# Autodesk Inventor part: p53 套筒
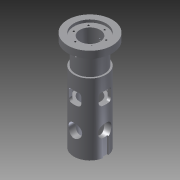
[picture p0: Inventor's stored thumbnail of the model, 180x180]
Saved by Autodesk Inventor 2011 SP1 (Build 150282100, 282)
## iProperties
Created: 2014-01
Part Number: p53 套筒
Document SubType Name: Modeling
Designer: Administrator
Density: 1 g/cm^3
Author: Administrator
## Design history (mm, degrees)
sketch "草图1"
  geometry: C1 r 47.5 at (0, 0); 1 further point
  constraints: 1 centre point, 1 coincident
  dimensions: "d0" = 95 diameter of C1
extrude "拉伸1" new body sketch "草图1" distance "d1" = 270; taper "d2" = 0 deg
hole "Hole1" diameter "d5" = 60; stored, may be unused: countersink angle "d9" = 90 deg, drill point angle "d11" = 118 deg; dims "d3" = 10, "d4" = 10, "d6" = 6, "d7" = 4, "d8" = 2, "d10" = 8
node "工作平面1"
sketch "草图2"
  geometry: L1 (-47.5, 0)-(47.5, 0) reference; L2 (-47.5, 270)-(47.5, 270) reference; L3 (47.5, 0)-(47.5, 270) reference; L4 (-47.5, 0)-(-47.5, 270) reference; L5 (8, 0)-(8, 48.67); L6 (-8, 0)-(-8, 48.67); L7 (-18, 134)-(18, 134); L8 (18, 134)-(18, 170); L9 (18, 170)-(-18, 170); L10 (-18, 170)-(-18, 134); A1 r 20 centre (0, 67) between (8, 48.67) and (-8, 48.67); 3 further points
  constraints: 12 end point, 4 parallel, 2 midpoint, 2 point on circle, 2 point on line, 1 centre point, 1 horizontal, 1 perpendicular, 1 vertical alignment
  dimensions: "d13" = 40 diameter of A1; "d14" = 67 distance of A1.centre point (0, 0); "d15" = 8 distance from line of point (0, 0) L5; "d16" = 16 distance between parallel lines of L6 L5; "d17" = 36 distance of L9.end L7.start; "d18" = 36 distance of L7.start L7.end; "d19" = 100 distance from line of point (0, 170) L2
extrude "拉伸2" cut sketch "草图2" stored distance "d20" = 270; taper "d21" = 0 deg
fillet "圆角1" dims "d22" = 8
fillet "圆角2" dims "d23" = 8
fillet "圆角3" dims "d24" = 8
fillet "圆角4" dims "d25" = 8
sketch "草图3"
  geometry: C1 r 46.5 at (0, 0); A1 r 30 centre (0, 0) between (28.914, 8) and (-28.914, 8) reference; A2 r 30 centre (0, 0) between (28.914, 8) and (-28.914, 8) reference
  constraints: 1 centre point, 1 coincident
  dimensions: "d26" = 93 diameter of C1
extrude "拉伸3" join sketch "草图3" distance "d27" = 4; taper "d28" = 0 deg
node "工作平面2"
sketch "草图4"
  geometry: C1 r 66 at (0, 0); 1 further point
  constraints: 1 centre point, 1 coincident
  dimensions: "d30" = 132 diameter of C1
extrude "拉伸4" join sketch "草图4" distance "d31" = 20; taper "d32" = 0 deg
hole "Hole3" diameter "d44" = 60; stored, may be unused: countersink angle "d48" = 90 deg, drill point angle "d50" = 0 deg; dims "d42" = 10, "d43" = 10, "d45" = 6, "d46" = 95, "d47" = 8, "d49" = 25
fillet "圆角5" dims "d51" = 0.5
fillet "圆角6" dims "d52" = 0.5
sketch "草图6" dims "d66" = 78
  geometry: C1 r 1.657 at (34.915, -17.377); A1 r 30 centre (0, 0) between (-28.914, -8) and (28.914, -8) reference; 1 further point
  constraints: 1 centre point, 1 coincident, 3 other
hole "Hole5" sketch "草图6" at (34.915, -17.377) diameter "d67" = 6.647; stored, may be unused: countersink angle "d71" = 90 deg, drill point angle "d73" = 118 deg; dims "d68" = 10, "d69" = 4, "d70" = 2, "d72" = 12
pattern_circular "环形阵列1" dims angle "d75" = 360 deg
node "工作平面3"
sketch "草图7"
  geometry: C1 r 39 at (0, 0); 1 further point
  constraints: 1 centre point, 1 coincident
  dimensions: "d78" = 78 diameter of C1
extrude "拉伸6" cut sketch "草图7" distance "d79" = 40; taper "d80" = 0 deg
node "工作平面4"
sketch "草图9" dims "d86" = 75
  geometry: C1 r 39 at (0, 0) reference; C2 r 1.479 at (35.278, 12.716); 1 further point
  constraints: 1 centre point, 1 coincident, 3 other
hole "Hole6" sketch "草图9" at (35.278, 12.716) diameter "d87" = 4.917; stored, may be unused: countersink angle "d91" = 90 deg, drill point angle "d93" = 118 deg; dims "d88" = 8, "d89" = 4, "d90" = 2, "d92" = 10
pattern_circular "环形阵列2" dims angle "d95" = 360 deg
node "工作平面5"
sketch "草图11"
  geometry: C1 r 42.5 at (0, 0); A1 r 47.5 centre (0, 0) between (46.821, 8) and (-46.821, 8) reference; A2 r 47.5 centre (0, 0) between (-46.821, -8) and (46.821, -8) reference; A3 r 47.5 centre (0, 0) between (43.957, -18) and (43.957, 18) reference; A4 r 47.5 centre (0, 0) between (-46.435, 10) and (-46.435, -10) reference; 1 further point
  constraints: 1 centre point, 1 coincident
  dimensions: "d101" = 85 diameter of C1
extrude "拉伸8" cut sketch "草图11" distance "d102" = 49; taper "d103" = 0 deg
sketch "草图12"
  geometry: L1 (29.897, 263.871)-(51.094, 255.318); L2 (51.094, 255.318)-(49.93, 252.433); L3 (49.93, 252.433)-(28.733, 260.986); L4 (28.733, 260.986)-(29.897, 263.871); 1 further point
  constraints: 8 end point, 2 parallel, 1 perpendicular
revolve "旋转2" sketch "草图12" stored, may be unused: angle "d104" = 90 deg
mirror "镜像3"
sketch "草图13"
  geometry: L1 (-85.228, 67)-(9.701, 67); L2 (28.914, 0)-(-28.914, 0) reference; C1 r 20 at (0, 67); 1 further point
  constraints: 2 end point, 1 centre point, 1 horizontal, 1 point on line
  dimensions: "d105" = 67 distance between parallel lines of L2 L1; "d106" = 40 diameter of C1
extrude "拉伸9" cut sketch "草图13" stored distance "d107" = 10; taper "d108" = 0 deg
fillet "圆角7" dims "d109" = 8
fillet "圆角8" dims "d110" = 8
fillet "圆角9" dims "d111" = 8
fillet "圆角10" dims "d112" = 8
sketch "草图14"
  geometry: L1 (49.401, 152)-(-40.899, 152); L2 (-66, 294)-(66, 294) reference; L3 (18, 169.351)-(-18, 169.351); L4 (-18, 169.351)-(-18, 133.351); L5 (-18, 133.351)-(18, 133.351); L6 (18, 133.351)-(18, 169.351); 3 further points
  constraints: 10 end point, 2 horizontal, 2 midpoint, 2 parallel, 1 perpendicular, 1 vertical alignment
  dimensions: "d113" = 142 distance between parallel lines of L1 L2; "d114" = 36 distance of L5.end L3.start; "d115" = 36 distance of L4.end L5.end
extrude "拉伸10" cut sketch "草图14" stored distance "d116" = 10; taper "d117" = 0 deg
fillet "圆角11" dims "d118" = 8
fillet "圆角12" dims "d119" = 8
fillet "圆角13" dims "d120" = 8
fillet "圆角14" dims "d121" = 8
fillet "圆角15" dims "d122" = 8
fillet "圆角16" dims "d123" = 8
fillet "圆角17" dims "d124" = 8
fillet "圆角18" dims "d125" = 8
node "工作平面6"
sketch "草图15"
  geometry: L1 (8, 48.67)-(8, 0) reference; L2 (-8, 0)-(-8, 48.67) reference; L3 (8, 0)-(-8, 0); L4 (40.935, 67)-(-50.322, 67); C1 r 20 at (0, 67); 1 further point
  constraints: 4 end point, 1 centre point, 1 horizontal alignment, 1 parallel, 1 perpendicular, 1 point on line
  dimensions: "d127" = 67 distance between parallel lines of L4 L3; "d128" = 40 diameter of C1
extrude "拉伸11" join sketch "草图15" stored distance "d129" = 10; taper "d130" = 0 deg
mirror "镜像4"
node "实体1"
other parameters: "d12" = -47.5, "d29" = 274, "d77" = 132, "d81" = 42.5, "d126" = 42.5
